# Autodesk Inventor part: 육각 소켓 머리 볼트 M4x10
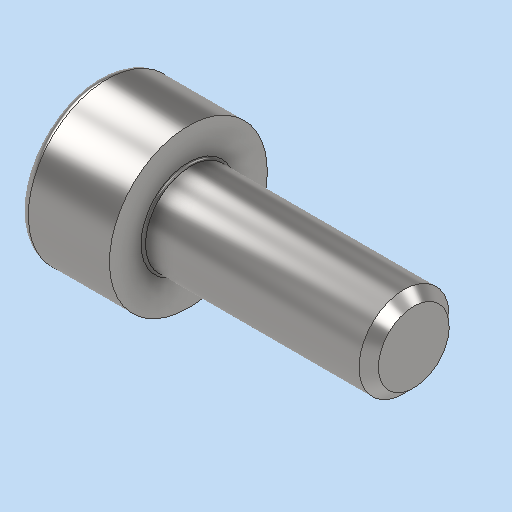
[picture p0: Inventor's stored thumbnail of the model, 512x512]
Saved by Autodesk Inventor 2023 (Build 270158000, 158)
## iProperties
Created: 2024-09
Part Number: 육각 소켓 머리 볼트 M4x10
Material: 강철, 연강
Description: 6각머리 태핑 나사
Document SubType Name: Modeling
Designer: asung
Density: 7.85 g/cm^3
Appearance: 기본값
Author: jhkim
Sending System: Autodesk Inventor 2025
Preprocessor: ST-DEVELOPER v20
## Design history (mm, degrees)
feature "Solid1"
node "솔리드1"
